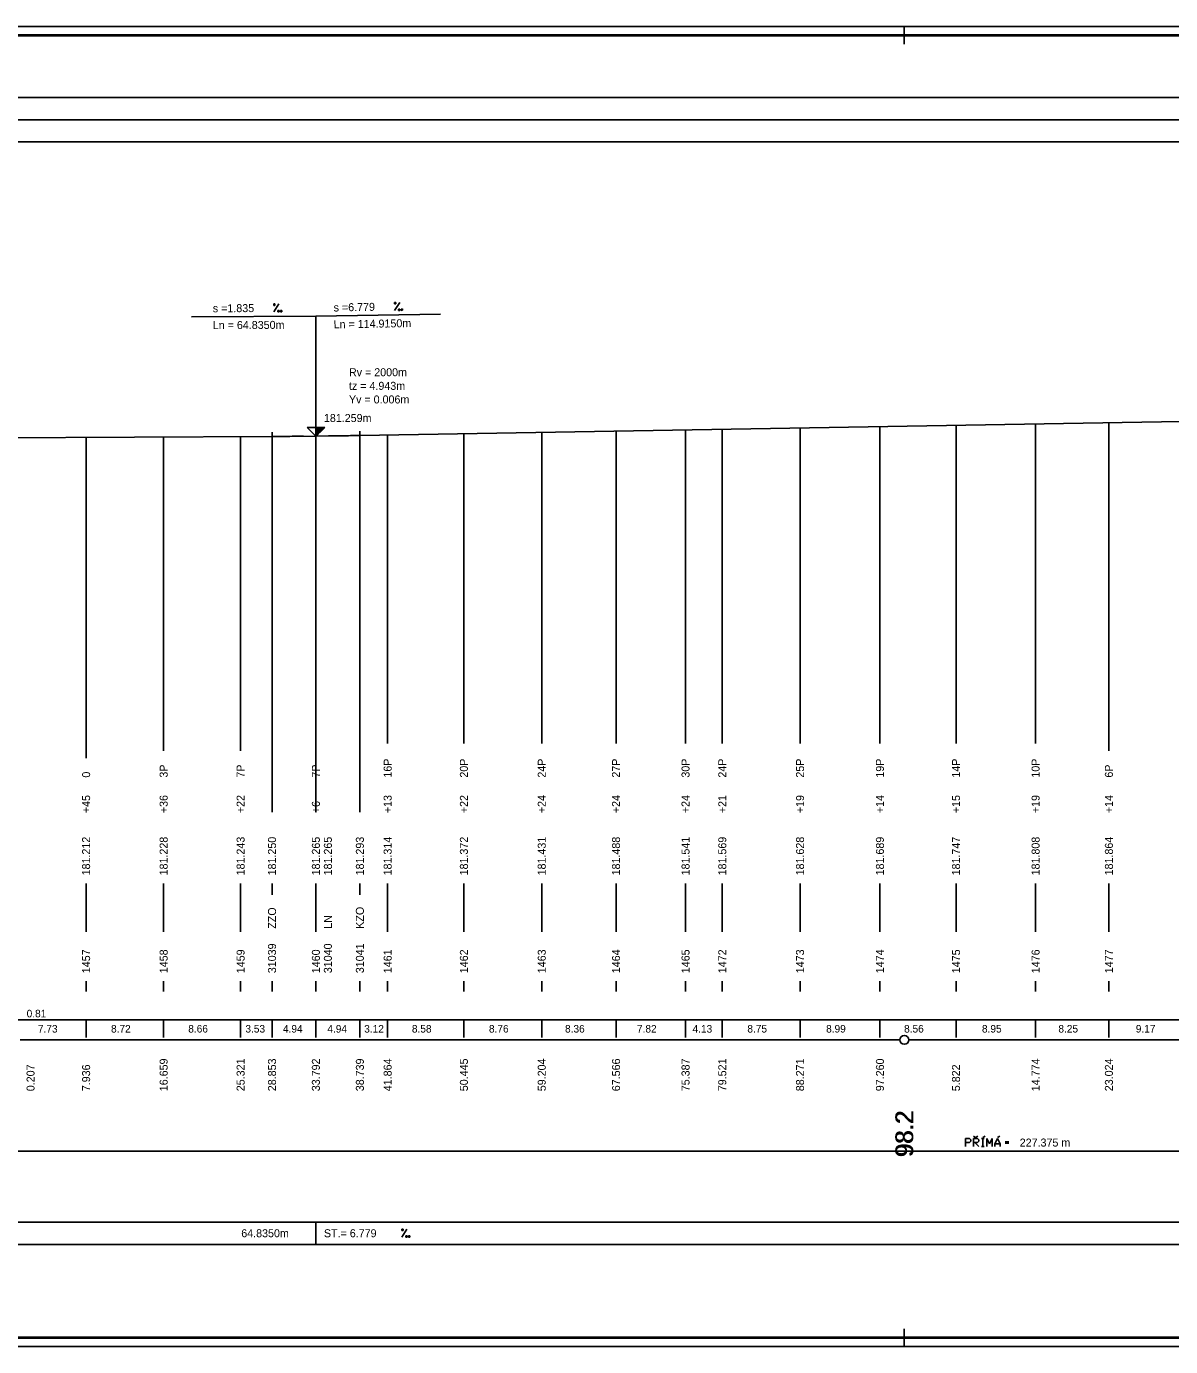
# Model space of a CAD drawing. Extents: x 0 to 10087, y -805 to 297.
# Drawn here: x 3582.4 to 3839.9, y 0 to 297 of the extents above; entities that cross this region are included whole.
import ezdxf

# ---------------------------------------------------------------- set-up
doc = ezdxf.new("R2010")
doc.units = 0
for name, color, linetype in [('CARKY_HODNOT', 7, 'Continuous'), ('KRIV1_CARA', 7, 'Continuous'), ('KRIV1_TEXT', 7, 'Continuous'), ('NIVELETA_CARA', 7, 'Continuous'), ('NIVELETA_TEXT', 7, 'Continuous'), ('RAM', 7, 'Continuous'), ('REZERVA', 7, 'Continuous'), ('STAN_CARA', 7, 'Continuous'), ('STAN_PAS', 7, 'Continuous'), ('STAN_TEXT', 7, 'Continuous'), ('TEXT', 7, 'Continuous'), ('TXT_C_BODU', 7, 'Continuous')]:
    doc.layers.add(name, color=color, linetype=linetype)

msp = doc.modelspace()

# ---------------------------------------------------------------- linework, layer by layer
at = {"layer": 'CARKY_HODNOT'}
for p, q in [((3657.48, 138.35), (3657.48, 204.96)), ((3663.73, 138.35), (3663.73, 205.07)), ((3680.89, 138.35), (3680.89, 205.36)), ((3698.41, 138.35), (3698.41, 205.66)), ((3715.13, 138.35), (3715.13, 205.94)), ((3730.77, 138.35), (3730.77, 206.2)), ((3739.04, 138.35), (3739.04, 206.34)), ((3756.54, 138.35), (3756.54, 206.64)), ((3774.52, 138.35), (3774.52, 206.95)), ((3791.64, 138.35), (3791.64, 207.24)), ((3809.55, 138.35), (3809.55, 207.54)), ((3826.05, 138.35), (3826.05, 207.82)), ((3595.87, 138.35), (3595.87, 204.56)), ((3613.32, 138.35), (3613.32, 204.64)), ((3630.64, 138.35), (3630.64, 204.72)), ((3637.71, 138.35), (3637.71, 204.75)), ((3647.58, 138.35), (3647.58, 204.83)), ((3647.59, 138.35), (3647.59, 204.83)), ((3595.87, 132.35), (3595.87, 138.35)), ((3613.32, 134), (3613.32, 138.35)), ((3630.64, 134), (3630.64, 138.35)), ((3637.71, 126.2), (3637.71, 138.35)), ((3647.58, 134), (3647.58, 138.35)), ((3647.59, 126.2), (3647.59, 138.35)), ((3657.48, 126.2), (3657.48, 138.35)), ((3663.73, 135.65), (3663.73, 138.35)), ((3680.89, 135.65), (3680.89, 138.35)), ((3698.41, 135.65), (3698.41, 138.35)), ((3715.13, 135.65), (3715.13, 138.35)), ((3730.77, 135.65), (3730.77, 138.35)), ((3739.04, 135.65), (3739.04, 138.35)), ((3756.54, 135.65), (3756.54, 138.35)), ((3774.52, 135.65), (3774.52, 138.35)), ((3791.64, 135.65), (3791.64, 138.35)), ((3809.55, 135.65), (3809.55, 138.35)), ((3826.05, 134), (3826.05, 138.35)), ((3637.71, 120.25), (3637.71, 126.2)), ((3647.59, 120.25), (3647.59, 126.2)), ((3657.48, 120.25), (3657.48, 126.2)), ((3595.87, 93.3), (3595.87, 104.2)), ((3613.32, 93.3), (3613.32, 104.2)), ((3630.64, 93.3), (3630.64, 104.2)), ((3637.71, 101.65), (3637.71, 104.2)), ((3647.58, 93.3), (3647.58, 104.2)), ((3647.59, 100), (3647.59, 104.2)), ((3657.48, 101.65), (3657.48, 104.2)), ((3663.73, 93.3), (3663.73, 104.2)), ((3680.89, 93.3), (3680.89, 104.2)), ((3698.41, 93.3), (3698.41, 104.2)), ((3715.13, 93.3), (3715.13, 104.2)), ((3730.77, 93.3), (3730.77, 104.2)), ((3739.04, 93.3), (3739.04, 104.2)), ((3756.54, 93.3), (3756.54, 104.2)), ((3774.52, 93.3), (3774.52, 104.2)), ((3791.64, 93.3), (3791.64, 104.2)), ((3809.55, 93.3), (3809.55, 104.2)), ((3826.05, 93.3), (3826.05, 104.2)), ((3595.87, 79.9), (3595.87, 82.2)), ((3613.32, 79.9), (3613.32, 82.2)), ((3630.64, 79.9), (3630.64, 82.2)), ((3637.71, 79.9), (3637.71, 82.2)), ((3647.58, 79.9), (3647.58, 82.2)), ((3647.59, 79.9), (3647.59, 82.2)), ((3657.48, 79.9), (3657.48, 82.2)), ((3663.73, 79.9), (3663.73, 82.2)), ((3680.89, 79.9), (3680.89, 82.2)), ((3698.41, 79.9), (3698.41, 82.2)), ((3715.13, 79.9), (3715.13, 82.2)), ((3730.77, 79.9), (3730.77, 82.2)), ((3739.04, 79.9), (3739.04, 82.2)), ((3756.54, 79.9), (3756.54, 82.2)), ((3774.52, 79.9), (3774.52, 82.2)), ((3791.64, 79.9), (3791.64, 82.2)), ((3809.55, 79.9), (3809.55, 82.2)), ((3826.05, 79.9), (3826.05, 82.2))]:
    msp.add_line(p, q, dxfattribs=at)
at = {"layer": 'KRIV1_CARA'}
msp.add_line((3580.41, 44), (4035.16, 44), dxfattribs=at)
at = {"layer": 'KRIV1_TEXT'}
for p, q in [((3793.76, 45), (3793.76, 46.8)), ((3793.76, 46.8), (3794.68, 46.8)), ((3794.67, 45.9), (3793.76, 45.9)), ((3794.98, 46.2), (3794.67, 45.9)), ((3794.68, 46.8), (3794.98, 46.49)), ((3794.98, 46.49), (3794.98, 46.2)), ((3796.05, 47.03), (3795.54, 47.37)), ((3795.56, 45), (3795.56, 46.8)), ((3795.56, 46.8), (3796.47, 46.8)), ((3796.47, 45.9), (3795.56, 45.9)), ((3795.86, 45.9), (3796.77, 45)), ((3796.05, 47.03), (3796.56, 47.37)), ((3796.47, 46.8), (3796.77, 46.51)), ((3796.77, 46.2), (3796.47, 45.9)), ((3796.77, 46.51), (3796.77, 46.2)), ((3797.4, 46.79), (3797.97, 46.79)), ((3797.4, 45), (3797.97, 45)), ((3797.68, 47.03), (3798.19, 47.37)), ((3797.69, 45), (3797.69, 46.79)), ((3798.57, 45), (3798.57, 46.79)), ((3798.57, 46.79), (3799.19, 45.6)), ((3799.19, 45.6), (3799.77, 46.79)), ((3799.77, 46.79), (3799.77, 45)), ((3800.98, 46.81), (3800.37, 45.6)), ((3800.37, 45), (3800.37, 45.6)), ((3800.37, 45.6), (3801.57, 45.6)), ((3801.57, 45.6), (3800.98, 46.81)), ((3801, 47.03), (3801.51, 47.37)), ((3801.57, 45.6), (3801.57, 45)), ((3802.69, 46.07), (3803.5, 46.07)), ((3802.69, 45.75), (3803.5, 45.75))]:
    msp.add_line(p, q, dxfattribs=at)
at = {"layer": 'NIVELETA_CARA'}
for p, q in [((300, 281), (8321.33, 281)), ((300, 276), (8321.33, 276)), ((300, 271), (8321.33, 271)), ((3647.59, 231.79), (3619.59, 231.67)), ((3647.59, 231.79), (3675.59, 232.27)), ((3647.59, 204.79), (3647.59, 231.79)), ((3657.48, 204.96), (3876.43, 208.67)), ((3637.71, 204.75), (3637.71, 205.75)), ((3647.59, 204.79), (3645.59, 206.79)), ((3645.59, 206.79), (3649.59, 206.79)), ((3647.59, 204.79), (3647.59, 206.79)), ((3649.59, 206.79), (3647.59, 204.79)), ((3647.59, 204.79), (3657.48, 204.96)), ((3647.66, 204.86), (3647.66, 206.79)), ((3647.73, 204.93), (3647.73, 206.79)), ((3647.79, 204.99), (3647.79, 206.79)), ((3647.86, 205.06), (3647.86, 206.79)), ((3647.93, 205.13), (3647.93, 206.79)), ((3647.99, 205.19), (3647.99, 206.79)), ((3648.06, 205.26), (3648.06, 206.79)), ((3648.13, 205.33), (3648.13, 206.79)), ((3648.19, 205.39), (3648.19, 206.79)), ((3648.26, 205.46), (3648.26, 206.79)), ((3648.33, 205.53), (3648.33, 206.79)), ((3648.39, 205.59), (3648.39, 206.79)), ((3648.46, 205.66), (3648.46, 206.79)), ((3648.53, 205.73), (3648.53, 206.79)), ((3648.59, 205.79), (3648.59, 206.79)), ((3648.66, 205.86), (3648.66, 206.79)), ((3648.73, 205.93), (3648.73, 206.79)), ((3648.79, 205.99), (3648.79, 206.79)), ((3648.86, 206.06), (3648.86, 206.79)), ((3648.93, 206.13), (3648.93, 206.79)), ((3648.99, 206.19), (3648.99, 206.79)), ((3649.06, 206.26), (3649.06, 206.79)), ((3649.13, 206.33), (3649.13, 206.79)), ((3649.19, 206.39), (3649.19, 206.79)), ((3649.26, 206.46), (3649.26, 206.79)), ((3649.33, 206.53), (3649.33, 206.79)), ((3649.39, 206.59), (3649.39, 206.79)), ((3649.46, 206.66), (3649.46, 206.79)), ((3649.53, 206.73), (3649.53, 206.79)), ((3655.39, 204.93), (3655.89, 204.94)), ((3655.89, 204.94), (3656.39, 204.94)), ((3656.39, 204.94), (3656.89, 204.95)), ((3656.89, 204.95), (3657.39, 204.96)), ((3657.39, 204.96), (3657.48, 204.96)), ((3657.48, 204.96), (3657.48, 205.96)), ((3521.71, 204.22), (3637.71, 204.75)), ((3637.71, 204.75), (3647.59, 204.79)), ((3637.71, 204.75), (3638.21, 204.75)), ((3638.21, 204.75), (3638.71, 204.75)), ((3638.71, 204.75), (3639.21, 204.76)), ((3639.21, 204.76), (3639.71, 204.76)), ((3639.71, 204.76), (3640.21, 204.76)), ((3640.21, 204.76), (3640.71, 204.77)), ((3640.71, 204.77), (3641.21, 204.77)), ((3641.21, 204.77), (3641.71, 204.77)), ((3641.71, 204.77), (3642.21, 204.78)), ((3642.21, 204.78), (3642.71, 204.78)), ((3642.71, 204.78), (3643.21, 204.78)), ((3643.21, 204.78), (3643.71, 204.79)), ((3643.71, 204.79), (3644.21, 204.79)), ((3644.21, 204.79), (3644.71, 204.8)), ((3644.71, 204.8), (3644.79, 204.8)), ((3650.39, 204.86), (3650.89, 204.86)), ((3650.89, 204.86), (3651.39, 204.87)), ((3651.39, 204.87), (3651.89, 204.88)), ((3651.89, 204.88), (3652.39, 204.88)), ((3652.39, 204.88), (3652.89, 204.89)), ((3652.89, 204.89), (3653.39, 204.9)), ((3653.39, 204.9), (3653.89, 204.91)), ((3653.89, 204.91), (3654.39, 204.91)), ((3654.39, 204.91), (3654.89, 204.92)), ((3654.89, 204.92), (3655.39, 204.93)), ((500, 28), (8321.33, 28)), ((3647.59, 23), (3647.59, 28)), ((500, 23), (8321.33, 23))]:
    msp.add_line(p, q, dxfattribs=at)
at = {"layer": 'NIVELETA_TEXT'}
for p, q in [((3665.26, 234.89), (3665.27, 234.59)), ((3665.27, 234.89), (3665.26, 234.89)), ((3665.56, 234.9), (3665.27, 234.89)), ((3665.29, 233.1), (3666.45, 234.91)), ((3665.56, 234.6), (3665.56, 234.9)), ((3638.09, 232.76), (3639.28, 234.55)), ((3638.09, 234.55), (3638.09, 234.25)), ((3638.38, 234.55), (3638.09, 234.55)), ((3638.09, 234.55), (3638.09, 234.54)), ((3638.09, 234.25), (3638.38, 234.25)), ((3638.38, 234.25), (3638.38, 234.55)), ((3639, 233.06), (3639, 232.76)), ((3639.01, 233.06), (3639, 233.05)), ((3639, 232.76), (3639.3, 232.76)), ((3639.3, 233.06), (3639.01, 233.06)), ((3639.3, 232.76), (3639.3, 233.06)), ((3639.62, 233.06), (3639.62, 232.76)), ((3639.91, 233.06), (3639.62, 233.06)), ((3639.62, 233.06), (3639.62, 233.05)), ((3639.62, 232.76), (3639.91, 232.76)), ((3639.91, 232.76), (3639.91, 233.06)), ((3665.27, 234.59), (3665.56, 234.6)), ((3666.2, 233.41), (3666.2, 233.11)), ((3666.49, 233.41), (3666.2, 233.41)), ((3666.2, 233.41), (3666.2, 233.4)), ((3666.2, 233.11), (3666.5, 233.12)), ((3666.5, 233.12), (3666.49, 233.41)), ((3666.81, 233.42), (3666.81, 233.12)), ((3666.82, 233.42), (3666.81, 233.41)), ((3666.81, 233.12), (3667.11, 233.13)), ((3667.11, 233.43), (3666.82, 233.42)), ((3667.11, 233.13), (3667.11, 233.43)), ((3666.89, 24.6), (3668.08, 26.4)), ((3666.89, 26.4), (3666.89, 26.1)), ((3666.9, 26.4), (3666.89, 26.39)), ((3666.89, 26.1), (3667.19, 26.1)), ((3667.19, 26.4), (3666.9, 26.4)), ((3667.19, 26.1), (3667.19, 26.4)), ((3667.8, 24.9), (3667.8, 24.6)), ((3667.81, 24.9), (3667.8, 24.89)), ((3667.8, 24.6), (3668.1, 24.6)), ((3668.1, 24.9), (3667.81, 24.9)), ((3668.1, 24.6), (3668.1, 24.9)), ((3668.42, 24.9), (3668.42, 24.6)), ((3668.71, 24.9), (3668.42, 24.9)), ((3668.42, 24.9), (3668.42, 24.89)), ((3668.42, 24.6), (3668.71, 24.6)), ((3668.71, 24.6), (3668.71, 24.9))]:
    msp.add_line(p, q, dxfattribs=at)
at = {"layer": 'RAM'}
for p, q in [((8636.33, 297), (0, 297)), ((3780, 293), (3780, 297)), ((8634.33, 295.1), (2, 295.1)), ((8634.33, 295), (2, 295)), ((8634.33, 294.9), (2, 294.9)), ((3780, 0), (3780, 4)), ((0, 0), (8636.33, 0)), ((2, 2.1), (8634.33, 2.1)), ((2, 2), (8634.33, 2)), ((2, 1.9), (8634.33, 1.9))]:
    msp.add_line(p, q, dxfattribs=at)
at = {"layer": 'REZERVA'}
msp.add_circle((3780, 69), 1, dxfattribs=at)
at = {"layer": 'STAN_CARA'}
for p, q in [((3581, 69), (3779, 69)), ((3781, 69), (3979, 69))]:
    msp.add_line(p, q, dxfattribs=at)
at = {"layer": 'STAN_PAS'}
for p, q in [((300, 73.5), (8321.33, 73.5)), ((3595.87, 69.5), (3595.87, 73.5)), ((3613.32, 69.5), (3613.32, 73.5)), ((3630.64, 69.5), (3630.64, 73.5)), ((3637.71, 69.5), (3637.71, 73.5)), ((3647.58, 69.5), (3647.58, 73.5)), ((3647.59, 69.5), (3647.59, 73.5)), ((3657.48, 69.5), (3657.48, 73.5)), ((3663.73, 69.5), (3663.73, 73.5)), ((3680.89, 69.5), (3680.89, 73.5)), ((3698.41, 69.5), (3698.41, 73.5)), ((3715.13, 69.5), (3715.13, 73.5)), ((3730.77, 69.5), (3730.77, 73.5)), ((3739.04, 69.5), (3739.04, 73.5)), ((3756.54, 69.5), (3756.54, 73.5)), ((3774.52, 69.5), (3774.52, 73.5)), ((3791.64, 69.5), (3791.64, 73.5)), ((3809.55, 69.5), (3809.55, 73.5)), ((3826.05, 69.5), (3826.05, 73.5))]:
    msp.add_line(p, q, dxfattribs=at)

# ---------------------------------------------------------------- texts
at = {"layer": 'KRIV1_TEXT'}
msp.add_text(' 227.375 m', height=1.8, dxfattribs=at).set_placement((3805.31, 45))
at = {"layer": 'NIVELETA_TEXT'}
for s, rotation, p in [('s =6.779', 0.9709, (3651.59, 232.86)), ('s =1.835', 0.2629, (3624.39, 232.69)), ('Ln = 64.8350m', 0.2629, (3624.39, 228.89)), ('Ln = 114.9150m', 0.9709, (3651.59, 229.06))]:
    msp.add_text(s, height=1.8, rotation=rotation, dxfattribs=at).set_placement(p)
for s, p in [('Rv = 2000m', (3655.03, 218.3)), ('tz = 4.943m', (3655.03, 215.24)), ('Yv = 0.006m', (3655.03, 212.18)), ('181.259m', (3649.39, 208)), ('64.8350m', (3630.79, 24.6)), ('ST.= 6.779', (3649.39, 24.6))]:
    msp.add_text(s, height=1.8, dxfattribs=at).set_placement(p)
at = {"layer": 'STAN_TEXT'}
for s, p in [('0.81', (3582.49, 74.07)), ('7.73', (3585.03, 70.65)), ('8.72', (3601.48, 70.65)), ('8.66', (3618.86, 70.65)), ('3.53', (3631.72, 70.65)), ('4.94', (3640.17, 70.64)), ('4.94', (3650.16, 70.63)), ('3.12', (3658.46, 70.64)), ('8.58', (3669.19, 70.65)), ('8.76', (3686.53, 70.65)), ('8.36', (3703.65, 70.65)), ('7.82', (3719.84, 70.65)), ('4.13', (3732.35, 70.63)), ('8.75', (3744.68, 70.65)), ('8.99', (3762.41, 70.65)), ('8.56', (3779.96, 70.65)), ('8.95', (3797.48, 70.65)), ('8.25', (3814.68, 70.65)), ('9.17', (3832.1, 70.65))]:
    msp.add_text(s, height=1.7, dxfattribs=at).set_placement(p)
for s, height, p in [('0.207', 1.8, (3584.27, 57.45)), ('7.936', 1.8, (3596.77, 57.45)), ('16.659', 1.8, (3614.22, 57.45)), ('25.321', 1.8, (3631.54, 57.45)), ('28.853', 1.8, (3638.61, 57.45)), ('33.792', 1.8, (3648.48, 57.45)), ('38.739', 1.8, (3658.38, 57.45)), ('41.864', 1.8, (3664.63, 57.45)), ('50.445', 1.8, (3681.79, 57.45)), ('59.204', 1.8, (3699.31, 57.45)), ('67.566', 1.8, (3716.03, 57.45)), ('75.387', 1.8, (3731.67, 57.45)), ('79.521', 1.8, (3739.94, 57.45)), ('88.271', 1.8, (3757.44, 57.45)), ('97.260', 1.8, (3775.42, 57.45)), ('5.822', 1.8, (3792.54, 57.45)), ('14.774', 1.8, (3810.45, 57.45)), ('23.024', 1.8, (3826.95, 57.45)), ('    98.2', 4, (3782, 36.84)), ('    98.2', 4, (3782, 36.74)), ('    98.2', 4, (3782, 36.64))]:
    msp.add_text(s, height=height, rotation=90, dxfattribs=at).set_placement(p)
at = {"layer": 'TEXT'}
for s, p in [('3P', (3614.22, 128)), ('7P', (3631.54, 128)), ('7P', (3648.48, 128)), ('16P', (3664.63, 128)), ('20P', (3681.79, 128)), ('24P', (3699.31, 128)), ('27P', (3716.03, 128)), ('30P', (3731.67, 128)), ('24P', (3739.94, 128)), ('25P', (3757.44, 128)), ('19P', (3775.42, 128)), ('14P', (3792.54, 128)), ('10P', (3810.45, 128)), ('6P', (3826.95, 128)), ('0', (3596.77, 128)), ('+45', (3596.77, 120)), ('+36', (3614.22, 120)), ('+22', (3631.54, 120)), ('+6', (3648.48, 120)), ('+13', (3664.63, 120)), ('+22', (3681.79, 120)), ('+24', (3699.31, 120)), ('+24', (3716.03, 120)), ('+24', (3731.67, 120)), ('+21', (3739.94, 120)), ('+19', (3757.44, 120)), ('+14', (3775.42, 120)), ('+15', (3792.54, 120)), ('+19', (3810.45, 120)), ('+14', (3826.95, 120)), ('181.212', (3596.77, 106)), ('181.228', (3614.22, 106)), ('181.243', (3631.54, 106)), ('181.250', (3638.61, 106)), ('181.265', (3648.48, 106)), ('181.265', (3651.18, 106)), ('181.293', (3658.38, 106)), ('181.314', (3664.63, 106)), ('181.372', (3681.79, 106)), ('181.431', (3699.31, 106)), ('181.488', (3716.03, 106)), ('181.541', (3731.67, 106)), ('181.569', (3739.94, 106)), ('181.628', (3757.44, 106)), ('181.689', (3775.42, 106)), ('181.747', (3792.54, 106)), ('181.808', (3810.45, 106)), ('181.864', (3826.95, 106)), ('ZZO', (3638.61, 94)), ('KZO', (3658.38, 94)), ('LN', (3651.18, 94))]:
    msp.add_text(s, height=1.8, rotation=90, dxfattribs=at).set_placement(p)
at = {"layer": 'TXT_C_BODU'}
for s, p in [('1457', (3596.77, 84)), ('1458', (3614.22, 84)), ('1459', (3631.54, 84)), ('31039', (3638.61, 84)), ('1460', (3648.48, 84)), ('31040', (3651.18, 84)), ('31041', (3658.38, 84)), ('1461', (3664.63, 84)), ('1462', (3681.79, 84)), ('1463', (3699.31, 84)), ('1464', (3716.03, 84)), ('1465', (3731.67, 84)), ('1472', (3739.94, 84)), ('1473', (3757.44, 84)), ('1474', (3775.42, 84)), ('1475', (3792.54, 84)), ('1476', (3810.45, 84)), ('1477', (3826.95, 84))]:
    msp.add_text(s, height=1.8, rotation=90, dxfattribs=at).set_placement(p)

doc.saveas('drawing.dxf')
